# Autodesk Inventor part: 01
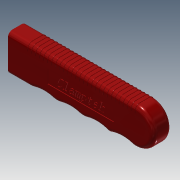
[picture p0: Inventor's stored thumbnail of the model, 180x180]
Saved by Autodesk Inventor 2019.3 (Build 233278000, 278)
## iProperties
Created: 2012-09
Part Number: 01
Material: Ogólny
Document SubType Name: Modeling
Designer: CADENGINEERING4
Density: 1 g/cm^3
Appearance: Czerwona
Author: CADENGINEERING4
Revision Number: ÈÎºÎ
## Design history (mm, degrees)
feature "ÇÐ³ý-À­Éì3"
node "Bryła1"
